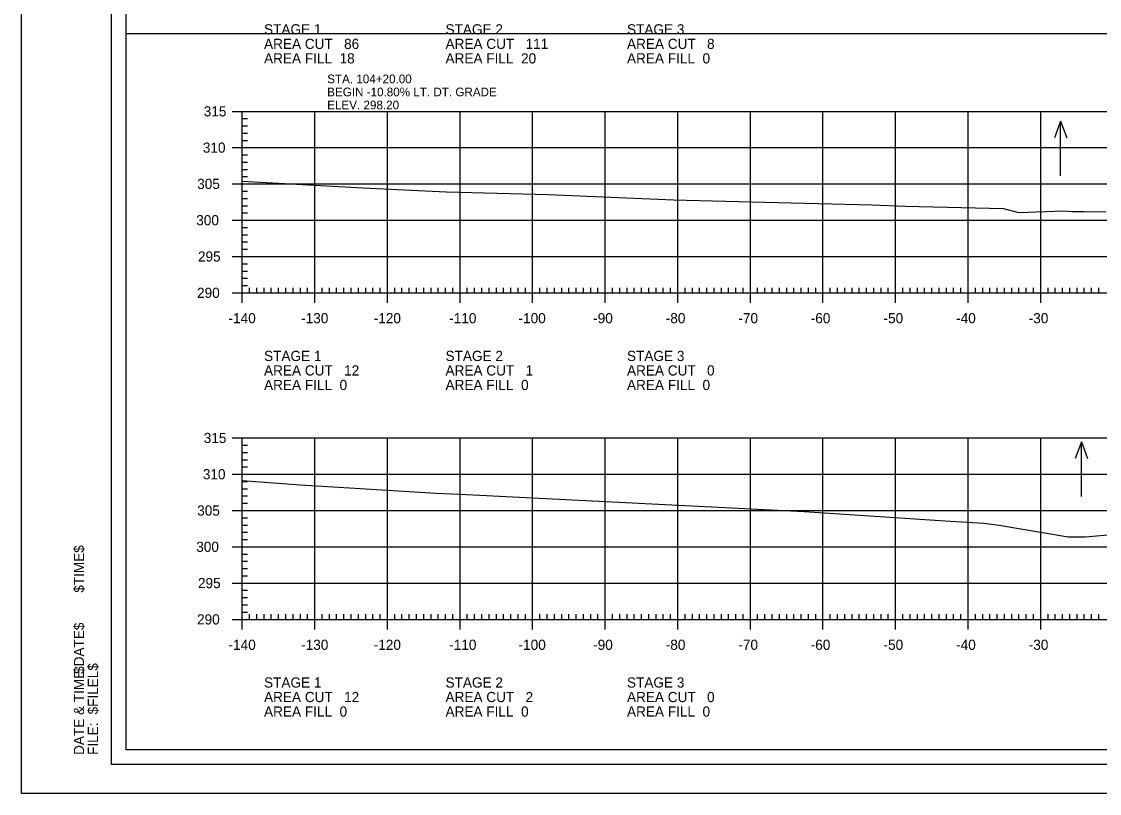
# Model space of a CAD drawing. Extents: x 1368713 to 1370673, y 380279 to 380950.
# Drawn here: x 1369981.9 to 1370130.4, y 380310.4 to 380416.8 of the extents above; entities that cross this region are included whole.
import ezdxf

# ---------------------------------------------------------------- set-up
doc = ezdxf.new("R2010")
doc.units = 0
for name, color, linetype in [('Notes', 7, 'Continuous'), ('R_Axis', 7, 'Continuous'), ('R_Axis Annot', 7, 'Continuous'), ('R_Border', 7, 'Continuous'), ('R_Border Notes', 7, 'Continuous'), ('R_Exist Surface', 7, 'Continuous'), ('R_Grid', 7, 'Continuous'), ('R_No Plot', 7, 'Continuous'), ('R_Water Annot', 7, 'Continuous')]:
    doc.layers.add(name, color=color, linetype=linetype)

msp = doc.modelspace()

# ---------------------------------------------------------------- linework, layer by layer
at = {"layer": 'R_Axis'}
for p, q in [((1370010.88, 380404.42), (1370013.68, 380404.42)), ((1370012.28, 380379.42), (1370012.28, 380404.42)), ((1370012.28, 380403.42), (1370012.98, 380403.42)), ((1370012.28, 380402.42), (1370012.98, 380402.42)), ((1370012.28, 380401.42), (1370012.98, 380401.42)), ((1370012.28, 380400.42), (1370012.98, 380400.42)), ((1370010.88, 380399.42), (1370013.68, 380399.42)), ((1370012.28, 380398.42), (1370012.98, 380398.42)), ((1370012.28, 380397.42), (1370012.98, 380397.42)), ((1370012.28, 380396.42), (1370012.98, 380396.42)), ((1370010.88, 380394.42), (1370013.68, 380394.42)), ((1370012.28, 380395.42), (1370012.98, 380395.42)), ((1370012.28, 380393.42), (1370012.98, 380393.42)), ((1370012.28, 380392.42), (1370012.98, 380392.42)), ((1370012.28, 380391.42), (1370012.98, 380391.42)), ((1370012.28, 380390.42), (1370012.98, 380390.42)), ((1370010.88, 380389.42), (1370013.68, 380389.42)), ((1370012.28, 380388.42), (1370012.98, 380388.42)), ((1370012.28, 380387.42), (1370012.98, 380387.42)), ((1370012.28, 380386.42), (1370012.98, 380386.42)), ((1370010.88, 380384.42), (1370013.68, 380384.42)), ((1370012.28, 380385.42), (1370012.98, 380385.42)), ((1370012.28, 380383.42), (1370012.98, 380383.42)), ((1370012.28, 380382.42), (1370012.98, 380382.42)), ((1370012.28, 380381.42), (1370012.98, 380381.42)), ((1370012.28, 380378.02), (1370012.28, 380380.82)), ((1370012.28, 380380.42), (1370012.98, 380380.42)), ((1370013.28, 380379.42), (1370013.28, 380380.12)), ((1370014.28, 380379.42), (1370014.28, 380380.12)), ((1370015.28, 380379.42), (1370015.28, 380380.12)), ((1370016.28, 380379.42), (1370016.28, 380380.12)), ((1370017.28, 380379.42), (1370017.28, 380380.12)), ((1370018.28, 380379.42), (1370018.28, 380380.12)), ((1370019.28, 380379.42), (1370019.28, 380380.12)), ((1370020.28, 380379.42), (1370020.28, 380380.12)), ((1370021.28, 380379.42), (1370021.28, 380380.12)), ((1370022.28, 380378.02), (1370022.28, 380380.82)), ((1370023.28, 380379.42), (1370023.28, 380380.12)), ((1370024.28, 380379.42), (1370024.28, 380380.12)), ((1370025.28, 380379.42), (1370025.28, 380380.12)), ((1370026.28, 380379.42), (1370026.28, 380380.12)), ((1370027.28, 380379.42), (1370027.28, 380380.12)), ((1370028.28, 380379.42), (1370028.28, 380380.12)), ((1370029.28, 380379.42), (1370029.28, 380380.12)), ((1370030.28, 380379.42), (1370030.28, 380380.12)), ((1370031.28, 380379.42), (1370031.28, 380380.12)), ((1370032.28, 380378.02), (1370032.28, 380380.82)), ((1370033.28, 380379.42), (1370033.28, 380380.12)), ((1370034.28, 380379.42), (1370034.28, 380380.12)), ((1370035.28, 380379.42), (1370035.28, 380380.12)), ((1370036.28, 380379.42), (1370036.28, 380380.12)), ((1370037.28, 380379.42), (1370037.28, 380380.12)), ((1370038.28, 380379.42), (1370038.28, 380380.12)), ((1370039.28, 380379.42), (1370039.28, 380380.12)), ((1370040.28, 380379.42), (1370040.28, 380380.12)), ((1370041.28, 380379.42), (1370041.28, 380380.12)), ((1370042.28, 380378.02), (1370042.28, 380380.82)), ((1370043.28, 380379.42), (1370043.28, 380380.12)), ((1370044.28, 380379.42), (1370044.28, 380380.12)), ((1370045.28, 380379.42), (1370045.28, 380380.12)), ((1370046.28, 380379.42), (1370046.28, 380380.12)), ((1370047.28, 380379.42), (1370047.28, 380380.12)), ((1370048.28, 380379.42), (1370048.28, 380380.12)), ((1370049.28, 380379.42), (1370049.28, 380380.12)), ((1370050.28, 380379.42), (1370050.28, 380380.12)), ((1370051.28, 380379.42), (1370051.28, 380380.12)), ((1370052.28, 380378.02), (1370052.28, 380380.82)), ((1370053.28, 380379.42), (1370053.28, 380380.12)), ((1370054.28, 380379.42), (1370054.28, 380380.12)), ((1370055.28, 380379.42), (1370055.28, 380380.12)), ((1370056.28, 380379.42), (1370056.28, 380380.12)), ((1370057.28, 380379.42), (1370057.28, 380380.12)), ((1370058.28, 380379.42), (1370058.28, 380380.12)), ((1370059.28, 380379.42), (1370059.28, 380380.12)), ((1370060.28, 380379.42), (1370060.28, 380380.12)), ((1370061.28, 380379.42), (1370061.28, 380380.12)), ((1370062.28, 380378.02), (1370062.28, 380380.82)), ((1370063.28, 380379.42), (1370063.28, 380380.12)), ((1370064.28, 380379.42), (1370064.28, 380380.12)), ((1370065.28, 380379.42), (1370065.28, 380380.12)), ((1370066.28, 380379.42), (1370066.28, 380380.12)), ((1370067.28, 380379.42), (1370067.28, 380380.12)), ((1370068.28, 380379.42), (1370068.28, 380380.12)), ((1370069.28, 380379.42), (1370069.28, 380380.12)), ((1370070.28, 380379.42), (1370070.28, 380380.12)), ((1370071.28, 380379.42), (1370071.28, 380380.12)), ((1370072.28, 380378.02), (1370072.28, 380380.82)), ((1370073.28, 380379.42), (1370073.28, 380380.12)), ((1370074.28, 380379.42), (1370074.28, 380380.12)), ((1370075.28, 380379.42), (1370075.28, 380380.12)), ((1370076.28, 380379.42), (1370076.28, 380380.12)), ((1370077.28, 380379.42), (1370077.28, 380380.12)), ((1370078.28, 380379.42), (1370078.28, 380380.12)), ((1370079.28, 380379.42), (1370079.28, 380380.12)), ((1370080.28, 380379.42), (1370080.28, 380380.12)), ((1370081.28, 380379.42), (1370081.28, 380380.12)), ((1370082.28, 380378.02), (1370082.28, 380380.82)), ((1370083.28, 380379.42), (1370083.28, 380380.12)), ((1370084.28, 380379.42), (1370084.28, 380380.12)), ((1370085.28, 380379.42), (1370085.28, 380380.12)), ((1370086.28, 380379.42), (1370086.28, 380380.12)), ((1370087.28, 380379.42), (1370087.28, 380380.12)), ((1370088.28, 380379.42), (1370088.28, 380380.12)), ((1370089.28, 380379.42), (1370089.28, 380380.12)), ((1370090.28, 380379.42), (1370090.28, 380380.12)), ((1370091.28, 380379.42), (1370091.28, 380380.12)), ((1370092.28, 380378.02), (1370092.28, 380380.82)), ((1370093.28, 380379.42), (1370093.28, 380380.12)), ((1370094.28, 380379.42), (1370094.28, 380380.12)), ((1370095.28, 380379.42), (1370095.28, 380380.12)), ((1370096.28, 380379.42), (1370096.28, 380380.12)), ((1370097.28, 380379.42), (1370097.28, 380380.12)), ((1370098.28, 380379.42), (1370098.28, 380380.12)), ((1370099.28, 380379.42), (1370099.28, 380380.12)), ((1370100.28, 380379.42), (1370100.28, 380380.12)), ((1370101.28, 380379.42), (1370101.28, 380380.12)), ((1370102.28, 380378.02), (1370102.28, 380380.82)), ((1370103.28, 380379.42), (1370103.28, 380380.12)), ((1370104.28, 380379.42), (1370104.28, 380380.12)), ((1370105.28, 380379.42), (1370105.28, 380380.12)), ((1370106.28, 380379.42), (1370106.28, 380380.12)), ((1370107.28, 380379.42), (1370107.28, 380380.12)), ((1370108.28, 380379.42), (1370108.28, 380380.12)), ((1370109.28, 380379.42), (1370109.28, 380380.12)), ((1370110.28, 380379.42), (1370110.28, 380380.12)), ((1370111.28, 380379.42), (1370111.28, 380380.12)), ((1370112.28, 380378.02), (1370112.28, 380380.82)), ((1370113.28, 380379.42), (1370113.28, 380380.12)), ((1370114.28, 380379.42), (1370114.28, 380380.12)), ((1370115.28, 380379.42), (1370115.28, 380380.12)), ((1370116.28, 380379.42), (1370116.28, 380380.12)), ((1370117.28, 380379.42), (1370117.28, 380380.12)), ((1370118.28, 380379.42), (1370118.28, 380380.12)), ((1370119.28, 380379.42), (1370119.28, 380380.12)), ((1370120.28, 380379.42), (1370120.28, 380380.12)), ((1370121.28, 380379.42), (1370121.28, 380380.12)), ((1370122.28, 380378.02), (1370122.28, 380380.82)), ((1370123.28, 380379.42), (1370123.28, 380380.12)), ((1370124.28, 380379.42), (1370124.28, 380380.12)), ((1370125.28, 380379.42), (1370125.28, 380380.12)), ((1370126.28, 380379.42), (1370126.28, 380380.12)), ((1370127.28, 380379.42), (1370127.28, 380380.12)), ((1370128.28, 380379.42), (1370128.28, 380380.12)), ((1370129.28, 380379.42), (1370129.28, 380380.12)), ((1370130.28, 380379.42), (1370130.28, 380380.12)), ((1370010.88, 380379.42), (1370013.68, 380379.42)), ((1370012.28, 380379.42), (1370292.28, 380379.42)), ((1370010.88, 380359.42), (1370013.68, 380359.42)), ((1370012.28, 380334.42), (1370012.28, 380359.42)), ((1370012.28, 380358.42), (1370012.98, 380358.42)), ((1370012.28, 380357.42), (1370012.98, 380357.42)), ((1370012.28, 380356.42), (1370012.98, 380356.42)), ((1370010.88, 380354.42), (1370013.68, 380354.42)), ((1370012.28, 380355.42), (1370012.98, 380355.42)), ((1370012.28, 380353.42), (1370012.98, 380353.42)), ((1370012.28, 380352.42), (1370012.98, 380352.42)), ((1370012.28, 380351.42), (1370012.98, 380351.42)), ((1370012.28, 380350.42), (1370012.98, 380350.42)), ((1370010.88, 380349.42), (1370013.68, 380349.42)), ((1370012.28, 380348.42), (1370012.98, 380348.42)), ((1370012.28, 380347.42), (1370012.98, 380347.42)), ((1370012.28, 380346.42), (1370012.98, 380346.42)), ((1370012.28, 380345.42), (1370012.98, 380345.42)), ((1370010.88, 380344.42), (1370013.68, 380344.42)), ((1370012.28, 380343.42), (1370012.98, 380343.42)), ((1370012.28, 380342.42), (1370012.98, 380342.42)), ((1370012.28, 380341.42), (1370012.98, 380341.42)), ((1370012.28, 380340.42), (1370012.98, 380340.42)), ((1370010.88, 380339.42), (1370013.68, 380339.42)), ((1370012.28, 380338.42), (1370012.98, 380338.42)), ((1370012.28, 380337.42), (1370012.98, 380337.42)), ((1370012.28, 380336.42), (1370012.98, 380336.42)), ((1370012.28, 380333.02), (1370012.28, 380335.82)), ((1370012.28, 380335.42), (1370012.98, 380335.42)), ((1370013.28, 380334.42), (1370013.28, 380335.12)), ((1370014.28, 380334.42), (1370014.28, 380335.12)), ((1370015.28, 380334.42), (1370015.28, 380335.12)), ((1370016.28, 380334.42), (1370016.28, 380335.12)), ((1370017.28, 380334.42), (1370017.28, 380335.12)), ((1370018.28, 380334.42), (1370018.28, 380335.12)), ((1370019.28, 380334.42), (1370019.28, 380335.12)), ((1370020.28, 380334.42), (1370020.28, 380335.12)), ((1370021.28, 380334.42), (1370021.28, 380335.12)), ((1370022.28, 380333.02), (1370022.28, 380335.82)), ((1370023.28, 380334.42), (1370023.28, 380335.12)), ((1370024.28, 380334.42), (1370024.28, 380335.12)), ((1370025.28, 380334.42), (1370025.28, 380335.12)), ((1370026.28, 380334.42), (1370026.28, 380335.12)), ((1370027.28, 380334.42), (1370027.28, 380335.12)), ((1370028.28, 380334.42), (1370028.28, 380335.12)), ((1370029.28, 380334.42), (1370029.28, 380335.12)), ((1370030.28, 380334.42), (1370030.28, 380335.12)), ((1370031.28, 380334.42), (1370031.28, 380335.12)), ((1370032.28, 380333.02), (1370032.28, 380335.82)), ((1370033.28, 380334.42), (1370033.28, 380335.12)), ((1370034.28, 380334.42), (1370034.28, 380335.12)), ((1370035.28, 380334.42), (1370035.28, 380335.12)), ((1370036.28, 380334.42), (1370036.28, 380335.12)), ((1370037.28, 380334.42), (1370037.28, 380335.12)), ((1370038.28, 380334.42), (1370038.28, 380335.12)), ((1370039.28, 380334.42), (1370039.28, 380335.12)), ((1370040.28, 380334.42), (1370040.28, 380335.12)), ((1370041.28, 380334.42), (1370041.28, 380335.12)), ((1370042.28, 380333.02), (1370042.28, 380335.82)), ((1370043.28, 380334.42), (1370043.28, 380335.12)), ((1370044.28, 380334.42), (1370044.28, 380335.12)), ((1370045.28, 380334.42), (1370045.28, 380335.12)), ((1370046.28, 380334.42), (1370046.28, 380335.12)), ((1370047.28, 380334.42), (1370047.28, 380335.12)), ((1370048.28, 380334.42), (1370048.28, 380335.12)), ((1370049.28, 380334.42), (1370049.28, 380335.12)), ((1370050.28, 380334.42), (1370050.28, 380335.12)), ((1370051.28, 380334.42), (1370051.28, 380335.12)), ((1370052.28, 380333.02), (1370052.28, 380335.82)), ((1370053.28, 380334.42), (1370053.28, 380335.12)), ((1370054.28, 380334.42), (1370054.28, 380335.12)), ((1370055.28, 380334.42), (1370055.28, 380335.12)), ((1370056.28, 380334.42), (1370056.28, 380335.12)), ((1370057.28, 380334.42), (1370057.28, 380335.12)), ((1370058.28, 380334.42), (1370058.28, 380335.12)), ((1370059.28, 380334.42), (1370059.28, 380335.12)), ((1370060.28, 380334.42), (1370060.28, 380335.12)), ((1370061.28, 380334.42), (1370061.28, 380335.12)), ((1370062.28, 380333.02), (1370062.28, 380335.82)), ((1370063.28, 380334.42), (1370063.28, 380335.12)), ((1370064.28, 380334.42), (1370064.28, 380335.12)), ((1370065.28, 380334.42), (1370065.28, 380335.12)), ((1370066.28, 380334.42), (1370066.28, 380335.12)), ((1370067.28, 380334.42), (1370067.28, 380335.12)), ((1370068.28, 380334.42), (1370068.28, 380335.12)), ((1370069.28, 380334.42), (1370069.28, 380335.12)), ((1370070.28, 380334.42), (1370070.28, 380335.12)), ((1370071.28, 380334.42), (1370071.28, 380335.12)), ((1370072.28, 380333.02), (1370072.28, 380335.82)), ((1370073.28, 380334.42), (1370073.28, 380335.12)), ((1370074.28, 380334.42), (1370074.28, 380335.12)), ((1370075.28, 380334.42), (1370075.28, 380335.12)), ((1370076.28, 380334.42), (1370076.28, 380335.12)), ((1370077.28, 380334.42), (1370077.28, 380335.12)), ((1370078.28, 380334.42), (1370078.28, 380335.12)), ((1370079.28, 380334.42), (1370079.28, 380335.12)), ((1370080.28, 380334.42), (1370080.28, 380335.12)), ((1370081.28, 380334.42), (1370081.28, 380335.12)), ((1370082.28, 380333.02), (1370082.28, 380335.82)), ((1370083.28, 380334.42), (1370083.28, 380335.12)), ((1370084.28, 380334.42), (1370084.28, 380335.12)), ((1370085.28, 380334.42), (1370085.28, 380335.12)), ((1370086.28, 380334.42), (1370086.28, 380335.12)), ((1370087.28, 380334.42), (1370087.28, 380335.12)), ((1370088.28, 380334.42), (1370088.28, 380335.12)), ((1370089.28, 380334.42), (1370089.28, 380335.12)), ((1370090.28, 380334.42), (1370090.28, 380335.12)), ((1370091.28, 380334.42), (1370091.28, 380335.12)), ((1370092.28, 380333.02), (1370092.28, 380335.82)), ((1370093.28, 380334.42), (1370093.28, 380335.12)), ((1370094.28, 380334.42), (1370094.28, 380335.12)), ((1370095.28, 380334.42), (1370095.28, 380335.12)), ((1370096.28, 380334.42), (1370096.28, 380335.12)), ((1370097.28, 380334.42), (1370097.28, 380335.12)), ((1370098.28, 380334.42), (1370098.28, 380335.12)), ((1370099.28, 380334.42), (1370099.28, 380335.12)), ((1370100.28, 380334.42), (1370100.28, 380335.12)), ((1370101.28, 380334.42), (1370101.28, 380335.12)), ((1370102.28, 380333.02), (1370102.28, 380335.82)), ((1370103.28, 380334.42), (1370103.28, 380335.12)), ((1370104.28, 380334.42), (1370104.28, 380335.12)), ((1370105.28, 380334.42), (1370105.28, 380335.12)), ((1370106.28, 380334.42), (1370106.28, 380335.12)), ((1370107.28, 380334.42), (1370107.28, 380335.12)), ((1370108.28, 380334.42), (1370108.28, 380335.12)), ((1370109.28, 380334.42), (1370109.28, 380335.12)), ((1370110.28, 380334.42), (1370110.28, 380335.12)), ((1370111.28, 380334.42), (1370111.28, 380335.12)), ((1370112.28, 380333.02), (1370112.28, 380335.82)), ((1370113.28, 380334.42), (1370113.28, 380335.12)), ((1370114.28, 380334.42), (1370114.28, 380335.12)), ((1370115.28, 380334.42), (1370115.28, 380335.12)), ((1370116.28, 380334.42), (1370116.28, 380335.12)), ((1370117.28, 380334.42), (1370117.28, 380335.12)), ((1370118.28, 380334.42), (1370118.28, 380335.12)), ((1370119.28, 380334.42), (1370119.28, 380335.12)), ((1370120.28, 380334.42), (1370120.28, 380335.12)), ((1370121.28, 380334.42), (1370121.28, 380335.12)), ((1370122.28, 380333.02), (1370122.28, 380335.82)), ((1370123.28, 380334.42), (1370123.28, 380335.12)), ((1370124.28, 380334.42), (1370124.28, 380335.12)), ((1370125.28, 380334.42), (1370125.28, 380335.12)), ((1370126.28, 380334.42), (1370126.28, 380335.12)), ((1370127.28, 380334.42), (1370127.28, 380335.12)), ((1370128.28, 380334.42), (1370128.28, 380335.12)), ((1370129.28, 380334.42), (1370129.28, 380335.12)), ((1370130.28, 380334.42), (1370130.28, 380335.12)), ((1370010.88, 380334.42), (1370013.68, 380334.42)), ((1370012.28, 380334.42), (1370292.28, 380334.42))]:
    msp.add_line(p, q, dxfattribs=at)
at = {"layer": 'R_Border'}
for p, q in [((1369994.28, 380314.42), (1369994.28, 380519.88)), ((1369994.28, 380314.42), (1369994.28, 380314.42)), ((1370310.46, 380314.42), (1369994.28, 380314.42))]:
    msp.add_line(p, q, dxfattribs=at)
at = {"layer": 'R_Exist Surface'}
for points in [[(1370012.28, 380394.79), (1370028.91, 380393.9), (1370040.39, 380393.35), (1370054.44, 380392.95), (1370071.7, 380392.23), (1370086.07, 380391.88), (1370099.05, 380391.54), (1370103.61, 380391.35), (1370117.15, 380391.04), (1370119.21, 380390.49), (1370125.39, 380390.69), (1370126.6, 380390.62), (1370128.18, 380390.61), (1370131.25, 380390.58)], [(1370012.28, 380353.57), (1370020.28, 380352.95), (1370039.01, 380351.83), (1370043.18, 380351.61), (1370089.7, 380349.3), (1370109.78, 380347.97), (1370114.43, 380347.69), (1370116.53, 380347.41), (1370126.07, 380345.81), (1370127.86, 380345.81), (1370128.46, 380345.81), (1370132.53, 380346.16)]]:
    msp.add_lwpolyline(points, dxfattribs=at)
at = {"layer": 'R_Grid'}
for p, q in [((1370012.28, 380404.42), (1370292.28, 380404.42)), ((1370012.28, 380379.42), (1370012.28, 380404.42)), ((1370022.28, 380379.42), (1370022.28, 380404.42)), ((1370032.28, 380379.42), (1370032.28, 380404.42)), ((1370042.28, 380379.42), (1370042.28, 380404.42)), ((1370052.28, 380379.42), (1370052.28, 380404.42)), ((1370062.28, 380379.42), (1370062.28, 380404.42)), ((1370072.28, 380379.42), (1370072.28, 380404.42)), ((1370082.28, 380379.42), (1370082.28, 380404.42)), ((1370092.28, 380379.42), (1370092.28, 380404.42)), ((1370102.28, 380379.42), (1370102.28, 380404.42)), ((1370112.28, 380379.42), (1370112.28, 380404.42)), ((1370122.28, 380379.42), (1370122.28, 380404.42)), ((1370012.28, 380399.42), (1370292.28, 380399.42)), ((1370012.28, 380394.42), (1370292.28, 380394.42)), ((1370012.28, 380389.42), (1370292.28, 380389.42)), ((1370012.28, 380384.42), (1370292.28, 380384.42)), ((1370012.28, 380379.42), (1370292.28, 380379.42)), ((1370012.28, 380359.42), (1370292.28, 380359.42)), ((1370012.28, 380334.42), (1370012.28, 380359.42)), ((1370022.28, 380334.42), (1370022.28, 380359.42)), ((1370032.28, 380334.42), (1370032.28, 380359.42)), ((1370042.28, 380334.42), (1370042.28, 380359.42)), ((1370052.28, 380334.42), (1370052.28, 380359.42)), ((1370062.28, 380334.42), (1370062.28, 380359.42)), ((1370072.28, 380334.42), (1370072.28, 380359.42)), ((1370082.28, 380334.42), (1370082.28, 380359.42)), ((1370092.28, 380334.42), (1370092.28, 380359.42)), ((1370102.28, 380334.42), (1370102.28, 380359.42)), ((1370112.28, 380334.42), (1370112.28, 380359.42)), ((1370122.28, 380334.42), (1370122.28, 380359.42)), ((1370012.28, 380354.42), (1370292.28, 380354.42)), ((1370012.28, 380349.42), (1370292.28, 380349.42)), ((1370012.28, 380344.42), (1370292.28, 380344.42)), ((1370012.28, 380339.42), (1370292.28, 380339.42)), ((1370012.28, 380334.42), (1370292.28, 380334.42))]:
    msp.add_line(p, q, dxfattribs=at)
at = {"layer": 'R_No Plot'}
for points in [[(1369981.88, 380523.77), (1370315.22, 380523.77), (1370315.22, 380310.43), (1369981.88, 380310.43)], [(1369996.28, 380517.88), (1370245.82, 380517.88), (1370245.82, 380508), (1370263.36, 380508), (1370287.46, 380508), (1370287.46, 380485.66), (1370308.46, 380485.66), (1370308.46, 380316.42), (1369996.28, 380316.42)], [(1369996.28, 380415.15), (1370308.46, 380415.15), (1370308.46, 380316.42), (1369996.28, 380316.42)]]:
    msp.add_lwpolyline(points, close=True, dxfattribs=at)
at = {"layer": 'R_Water Annot'}
for p, q in [((1370125.01, 380403.08), (1370124.16, 380400.78)), ((1370125.01, 380395.54), (1370125.01, 380403.08)), ((1370125.01, 380403.08), (1370125.85, 380400.78)), ((1370127.88, 380358.9), (1370127.04, 380356.6)), ((1370127.88, 380351.36), (1370127.88, 380358.9)), ((1370127.88, 380358.9), (1370128.72, 380356.6))]:
    msp.add_line(p, q, dxfattribs=at)

# ---------------------------------------------------------------- texts
at = {"layer": 'Notes'}
for s, p in [('STA. 104+20.00', (1370023.98, 380408.29)), ('BEGIN -10.80% LT. DT. GRADE', (1370023.98, 380406.49)), ('ELEV. 298.20', (1370023.98, 380404.69))]:
    msp.add_text(s, height=1.2, dxfattribs=at).set_placement(p)
at = {"layer": 'R_Axis Annot'}
for s, p in [('STAGE 1', (1370015.28, 380415.02)), ('STAGE 2', (1370040.28, 380415.02)), ('STAGE 3', (1370065.28, 380415.02)), ('AREA CUT   86', (1370015.28, 380413.02)), ('AREA CUT   111', (1370040.28, 380413.02)), ('AREA CUT   8', (1370065.28, 380413.02)), ('AREA FILL  18', (1370015.28, 380411.02)), ('AREA FILL  20', (1370040.28, 380411.02)), ('AREA FILL  0', (1370065.28, 380411.02)), ('315', (1370006.97, 380403.72)), ('310', (1370006.85, 380398.72)), ('305', (1370006.07, 380393.72)), ('300', (1370005.94, 380388.72)), ('295', (1370006.18, 380383.72)), ('290', (1370006.05, 380378.72)), ('-140', (1370010.39, 380375.22)), ('-130', (1370020.39, 380375.22)), ('-120', (1370030.39, 380375.22)), ('-110', (1370040.79, 380375.22)), ('-100', (1370050.34, 380375.22)), ('-90', (1370060.62, 380375.22)), ('-80', (1370070.62, 380375.22)), ('-70', (1370080.62, 380375.22)), ('-60', (1370090.59, 380375.22)), ('-50', (1370100.62, 380375.22)), ('-40', (1370110.62, 380375.22)), ('-30', (1370120.62, 380375.22)), ('STAGE 1', (1370015.28, 380370.02)), ('STAGE 2', (1370040.28, 380370.02)), ('STAGE 3', (1370065.28, 380370.02)), ('AREA CUT   12', (1370015.28, 380368.02)), ('AREA CUT   1', (1370040.28, 380368.02)), ('AREA CUT   0', (1370065.28, 380368.02)), ('AREA FILL  0', (1370015.28, 380366.02)), ('AREA FILL  0', (1370040.28, 380366.02)), ('AREA FILL  0', (1370065.28, 380366.02)), ('315', (1370006.97, 380358.72)), ('310', (1370006.85, 380353.72)), ('305', (1370006.07, 380348.72)), ('300', (1370005.94, 380343.72)), ('295', (1370006.18, 380338.72)), ('290', (1370006.05, 380333.72)), ('-140', (1370010.39, 380330.22)), ('-130', (1370020.39, 380330.22)), ('-120', (1370030.39, 380330.22)), ('-110', (1370040.79, 380330.22)), ('-100', (1370050.34, 380330.22)), ('-90', (1370060.62, 380330.22)), ('-80', (1370070.62, 380330.22)), ('-70', (1370080.62, 380330.22)), ('-60', (1370090.59, 380330.22)), ('-50', (1370100.62, 380330.22)), ('-40', (1370110.62, 380330.22)), ('-30', (1370120.62, 380330.22)), ('STAGE 1', (1370015.28, 380325.02)), ('STAGE 2', (1370040.28, 380325.02)), ('STAGE 3', (1370065.28, 380325.02)), ('AREA CUT   12', (1370015.28, 380323.02)), ('AREA CUT   2', (1370040.28, 380323.02)), ('AREA CUT   0', (1370065.28, 380323.02)), ('AREA FILL  0', (1370015.28, 380321.02)), ('AREA FILL  0', (1370040.28, 380321.02)), ('AREA FILL  0', (1370065.28, 380321.02))]:
    msp.add_text(s, height=1.4, dxfattribs=at).set_placement(p)
at = {"layer": 'R_Border Notes'}
for s, height, p in [('$TIME$', 1.397, (1369990.48, 380338.09)), ('$DATE$', 1.397, (1369990.48, 380326.91)), ('DATE & TIME:', 1.3968, (1369990.48, 380315.74)), ('$FILEL$', 1.397, (1369992.4, 380321.32)), ('FILE: ', 1.397, (1369992.4, 380315.74))]:
    msp.add_text(s, height=height, rotation=90, dxfattribs=at).set_placement(p)

doc.saveas('drawing.dxf')
